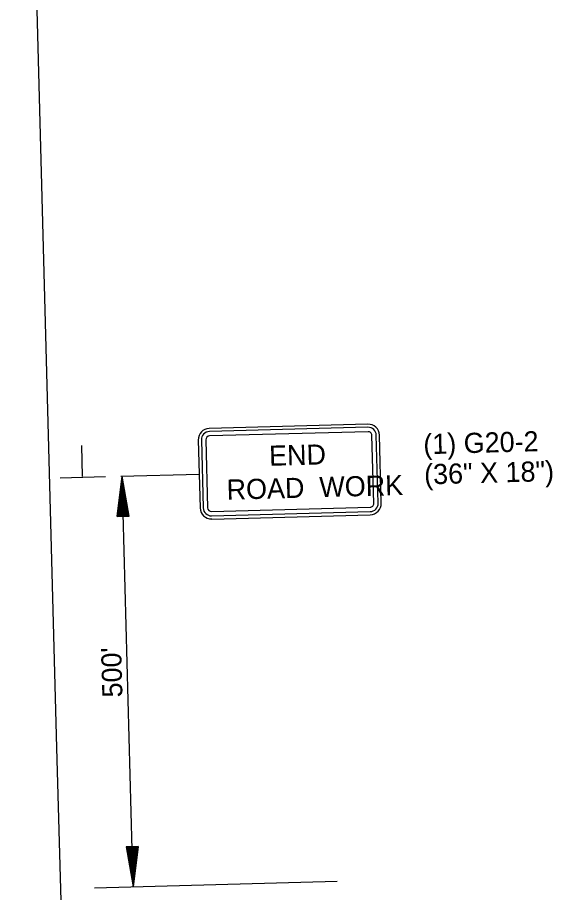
# Model space of a CAD drawing. Extents: x 1929653 to 1931621, y 596452 to 600944.
# Drawn here: x 1930875.7 to 1931035.1, y 600466.9 to 600727.6 of the extents above; entities that cross this region are included whole.
import ezdxf

# ---------------------------------------------------------------- set-up
doc = ezdxf.new("R2010")
doc.units = 0
for name, color, linetype in [('P_TC_Signs_Temporary', 7, 'Continuous'), ('R_Border', 7, 'Continuous'), ('R_Draft', 7, 'Continuous')]:
    doc.layers.add(name, color=color, linetype=linetype)

msp = doc.modelspace()

# ---------------------------------------------------------------- linework, layer by layer
at = {"layer": 'P_TC_Signs_Temporary'}
for p, q in [((1930980.12, 600606.44), (1930932.88, 600605.17)), ((1930980.14, 600605.5), (1930932.91, 600604.24)), ((1930980.18, 600604.19), (1930932.94, 600602.92)), ((1930929.6, 600601.71), (1930930.14, 600581.47)), ((1930930.54, 600601.73), (1930931.08, 600581.49)), ((1930931.85, 600601.77), (1930932.39, 600581.53)), ((1930981.87, 600582.86), (1930981.33, 600603.1)), ((1930983.19, 600582.89), (1930982.64, 600603.13)), ((1930984.12, 600582.92), (1930983.58, 600603.16)), ((1930933.55, 600580.43), (1930980.78, 600581.7)), ((1930933.58, 600579.12), (1930980.81, 600580.39)), ((1930933.61, 600578.18), (1930980.84, 600579.45))]:
    msp.add_line(p, q, dxfattribs=at)
for centre, radius, start, end in [((1930980.21, 600603.07), 3.37, 1.5377, 91.5377), ((1930932.97, 600601.8), 3.38, 91.5377, 181.5377), ((1930932.97, 600601.8), 2.44, 91.5377, 181.5377), ((1930980.21, 600603.07), 2.44, 1.5377, 91.5377), ((1930980.21, 600603.07), 1.13, 1.5377, 91.5377), ((1930932.97, 600601.8), 1.13, 91.5377, 181.5377), ((1930980.75, 600582.83), 1.13, 271.5377, 1.5377), ((1930980.75, 600582.83), 2.44, 271.5377, 1.5377), ((1930980.75, 600582.83), 3.37, 271.5377, 1.5377), ((1930933.52, 600581.56), 3.37, 181.5377, 271.5377), ((1930933.52, 600581.56), 2.44, 181.5377, 271.5377), ((1930933.52, 600581.56), 1.13, 181.5377, 271.5377)]:
    msp.add_arc(centre, radius, start, end, dxfattribs=at)
at = {"layer": 'R_Draft'}
for p, q in [((1930875.75, 600943.92), (1930887.39, 600510.06)), ((1930895.16, 600590.85), (1930894.92, 600600.04)), ((1930888.47, 600590.48), (1930901.93, 600590.84)), ((1930905.44, 600578.97), (1930906.92, 600590.98)), ((1930906.58, 600590.96), (1930929.87, 600591.59)), ((1930910.2, 600468.65), (1930906.92, 600590.98)), ((1930909.03, 600579.06), (1930906.92, 600590.98)), ((1930905.74, 600578.98), (1930906.97, 600588.98)), ((1930908.74, 600579.06), (1930906.97, 600588.98)), ((1930906.05, 600578.98), (1930907.03, 600586.92)), ((1930908.43, 600579.05), (1930907.03, 600586.92)), ((1930906.35, 600578.99), (1930907.08, 600584.94)), ((1930906.66, 600579), (1930907.14, 600582.9)), ((1930908.13, 600579.04), (1930907.08, 600584.94)), ((1930907.82, 600579.03), (1930907.14, 600582.9)), ((1930906.96, 600579.01), (1930907.19, 600580.91)), ((1930907.52, 600579.02), (1930907.19, 600580.91)), ((1930905.44, 600578.97), (1930909.03, 600579.06)), ((1930887.39, 600510.06), (1930890.03, 600411.86)), ((1930911.68, 600480.67), (1930908.09, 600480.57)), ((1930908.09, 600480.57), (1930910.2, 600468.65)), ((1930908.39, 600480.58), (1930910.15, 600470.65)), ((1930908.69, 600480.59), (1930910.09, 600472.71)), ((1930908.99, 600480.59), (1930910.04, 600474.7)), ((1930909.3, 600480.6), (1930909.99, 600476.73)), ((1930909.6, 600480.61), (1930909.93, 600478.73)), ((1930910.16, 600480.63), (1930909.93, 600478.73)), ((1930910.46, 600480.63), (1930909.99, 600476.73)), ((1930910.77, 600480.64), (1930910.04, 600474.7)), ((1930911.07, 600480.65), (1930910.09, 600472.71)), ((1930911.38, 600480.66), (1930910.15, 600470.65)), ((1930911.68, 600480.67), (1930910.2, 600468.65)), ((1930898.67, 600468.34), (1930970.96, 600470.28))]:
    msp.add_line(p, q, dxfattribs=at)

# ---------------------------------------------------------------- texts
at = {"layer": 'P_TC_Signs_Temporary'}
for s, p in [('END', (1930950.78, 600594.03)), ('ROAD  WORK', (1930938.12, 600583.93))]:
    msp.add_text(s, height=6, rotation=1.5377, dxfattribs=at).set_placement(p)
at = {"layer": 'R_Border'}
for s, p in [('(1) G20-2', (1930996.73, 600597.47)), ('(36" X 18")', (1930996.97, 600588.48))]:
    msp.add_text(s, height=6, rotation=1.5377, dxfattribs=at).set_placement(p)
at = {"layer": 'R_Draft'}
msp.add_text("500'", height=6, rotation=91.5377, dxfattribs=at).set_placement((1930907.03, 600525.1))

doc.saveas('drawing.dxf')
